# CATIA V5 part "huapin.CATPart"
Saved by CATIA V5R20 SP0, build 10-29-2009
Part number: VASE
Material "Cloudy Sky"
Material "Light Green": density 7860 kg/m3, Young's modulus 2e+11 Pa, Poisson ratio 0.266
Material "Epoxy": density 1300 kg/m3, Young's modulus 3e+09 Pa, Poisson ratio 0.37, thermal expansion 6e-05 1/K
Material "Copper": density 8900 kg/m3, Young's modulus 1.1e+11 Pa, Poisson ratio 0.33, thermal expansion 1.65e-05 1/K
Bounding box of the stored display mesh (mm): x -40 to 40, y -40 to 59.343, z 0 to 112.994
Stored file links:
  C:\Users\ysz\Desktop\新建文件夹\huapin.CATPart
  D:\CATIAR20\win_b64\startup\materials\Catalog.CATMaterial
  D:\CATIAR20\win_b64\startup\materials\brushed_metal2.jpg
  D:\CATIAR20\win_b64\startup\materials\red_env_512x512.jpg
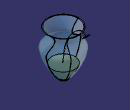
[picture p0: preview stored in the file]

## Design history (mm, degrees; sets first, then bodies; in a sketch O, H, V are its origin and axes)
Body1 (main body), material "Cloudy Sky"
  Plane1: type Offset, RefPlane xy-plane, Offset 20
  Plane2: type Offset, RefPlane Plane1, Offset 20
  Plane3: type Offset, RefPlane Plane2, Offset 20
  Plane4: type Offset, RefPlane Plane3, Offset 20
  Plane5: type Offset, RefPlane Plane4, Offset 20
  Sketch1 on Plane5, origin (0, 0, 100), H (1, 0, 0), V (0, 1, 0)
    circle A1 centre (0, 0) radius 35
    radius A1 = 35
  Sketch2 on Plane4, origin (0, 0, 80), H (1, 0, 0), V (0, 1, 0)
    circle A1 centre (0, 0) radius 20
    point P1 (20, 0)
    radius A1 = 20
    coincidence: A1 P1, P1 H
  Sketch3 on Plane3, origin (0, 0, 60), H (1, 0, 0), V (0, 1, 0)
    circle A1 centre (0, 0) radius 40
    radius A1 = 40
  Sketch4 on Plane2, origin (0, 0, 40), H (1, 0, 0), V (0, 1, 0)
    circle A1 centre (0, 0) radius 35
    radius A1 = 35
  Sketch5 on Plane1, origin (0, 0, 20), H (1, 0, 0), V (0, 1, 0)
    circle A1 centre (0, 0) radius 25
    radius A1 = 25
  Sketch6 on xy-plane, origin (0, 0, 0), H (1, 0, 0), V (0, 1, 0)
    circle A1 centre (0, 0) radius 10
    radius A1 = 10
  Loft1: solid, Sections (Sketch1; Sketch2; Sketch3; Sketch4; Sketch5; Sketch6)
  Shell1: IntOffset 1, Face face of Loft1, ExtOffset 0
  Sketch7 on yz-plane, origin (0, 0, 0), H (0, 1, 0), V (0, 0, 1)
    line L1 (0, 0) -> (10, 0)
    horizontal: L1 H
Body2, material "Light Green"
  Sketch8 on yz-plane, origin (0, 0, 0), H (0, 1, 0), V (0, 0, 1)
    point P1 (0, 28.5666)
    line L1 (0, 28.5666) -> (25.8471, 28.5666)
    point P2 (25.8471, 28.5666)
    spline S1 through (25.8471, 28.5666) (18.6544, 13.9546) (6.9833, 0)
    line L2 (6.9833, 0) -> (0, 0)
    line L3 (0, 0) -> (0, 28.5666)
    point P3 (6.9833, 0)
    point P4 (25.8471, 28.5666)
    point P5 (6.9833, 0)
    coincidence: P1 V, P4 P2, P5 H, P5 P3
    horizontal: L1 H, L2 H
    vertical: L3 V
  Shaft1: profile Sketch8, axis Z axis, angle 360
Body3, material "Copper"
  Sketch9 on yz-plane, origin (0, 0, 0), H (0, 1, 0), V (0, 0, 1)
    spline S1 through (-1.8593, 25.2839) (3.0263, 58.8372) (16.4615, 91.8494) (48.0819, 111.0614) (52.8317, 107.2731)
  Plane6: type Normal, Curve Sketch9, RefPoint vertex of Sketch9
  Sketch10 on Plane6, origin (0, -29.8732, 33.4816), H (1, 0, 0), V (0, 0.7462, 0.6658)
    circle A1 centre (0, 110.839) radius 0.7
    point P1 (0, 110.839)
    reference projected point E1 (0, 110.839) from vertex of Sketch9
    radius A1 = 0.7
    coincidence: P1 V, P1 E1
  Rib1: profile Sketch10, centre curve Sketch9
Body4, material "Epoxy"
  Sketch11 on Plane6, origin (0, -29.8732, 33.4816), H (1, 0, 0), V (0, 0.7462, 0.6658)
    spline S1 through (0, 104.3925) (-8.5033, 106.2866) (-3.6903, 115.8833) (7.8357, 117.5249) (7.8357, 106.2866) (0, 104.3925)
    point P1 (0, 104.3925)
    point P2 (0, 104.3925)
    coincidence: P1 V, P2 P1
  Pad1: profile Sketch11, direction (0, 0.6658, -0.7462), length 0.5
